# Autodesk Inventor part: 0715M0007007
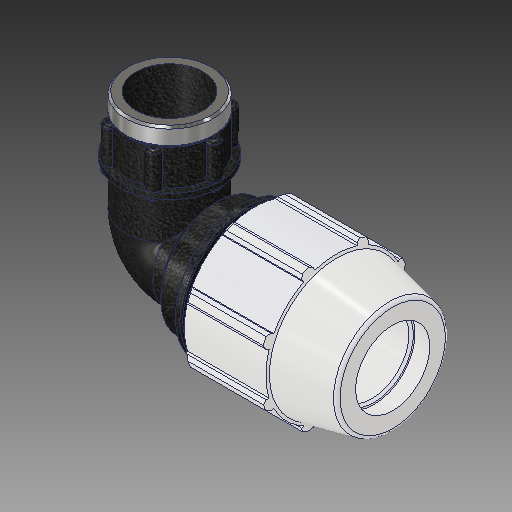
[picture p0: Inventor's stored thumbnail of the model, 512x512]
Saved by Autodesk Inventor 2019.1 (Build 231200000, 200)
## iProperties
Created: 2017-02
Part Number: 0715M0007007
Material: PVC-Piping
Description: PLASSON 90° ELBOW FEMALE ADAPTOR 3/4'' - 3/4''F
Document SubType Name: Modeling
Designer: KIM
Mass: 92.6774 g
Surface Area: 199.44 cm^2
Volume: 66.1981 cm^3
Density: 1.4 g/cm^3
Appearance: PTFE
Author: KIM
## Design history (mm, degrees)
derived "0715M0.ipt"
feature "Solid1::0715M0.ipt"
tag "TaggingFeature1"
body "Solid1"
other parameters: "d2" = 26.6, "d4" = 6.6675, "d5" = 20.0025, "d7" = 54.102, "d9" = 11.43, "d11" = 2.667, "d13" = 120 deg, "d14" = 39.9, "d15" = 12 deg, "d16" = 47.06874, "d18" = 1.33, "d19" = 35 deg, "d20" = 17.5 deg, "d21" = 50.31486, "d23" = 0, "d25" = 360 deg, "d27" = 1.08204, "d33" = 0.532, "d42" = 29.6037, "d43" = 1.62306, "d46" = 0.798, "d51" = 80.01, "d68" = 2.667, "d72" = 45.974, "d73" = 31.3521, "d74" = 19.05, "d75" = 36.05492, "d76" = 24.117, "d77" = 20.955, "d79" = 9.6468, "d80" = 0.72351, "d83" = 0, "d84" = 0, "d91" = 40.5765, "d93" = 56.896, "d94" = 24.117, "d95" = 16.8819, "d96" = 8.001, "d97" = 50 deg, "d98" = 21.7053, "d99" = 0.5, "d100" = 0.5, "d101" = 6.35, "d102" = 31.3521, "d103" = 16.1925, "d104" = 0, "d108" = 360 deg, "d110" = 0.94056, "d_" = 26.6, "E_" = 54.102, "A_" = 80.01, "l_" = 56.896, "l_2" = 19.05, "A_1" = 45.974, "G_" = 24.117, "d105" = 4.70281
